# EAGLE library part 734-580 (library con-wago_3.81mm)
Serie 734, Federleiste mit abgewinkelten Einlötstiften / Series 734, Female connector with angled solder pins Polzahl / Pole No.: 20 Bemessungsspannung / Rated Voltage: 160 V Nennstrom / Nominal Current: 10 A Lötstiftlänge: / Solder Pin Length: 3.8 mm Farbe / Color: orange / orange Stand: 01.01.2012. Die jeweils aktuellen Daten zu diesem Artikel finden Sie in unserem Produktkatalog, den Sie unter www.wago.com einsehen können. As of: 01/01/2012. Please find the newest data for this article in our product catalogue, which can be viewed under www.wago.com.
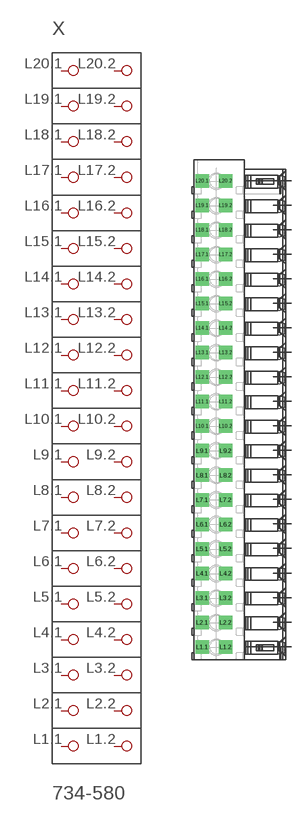
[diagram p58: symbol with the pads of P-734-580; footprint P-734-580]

Designator prefix X

## 734-580  [P-734-580]
L1.1  P1.1
L1.2  P1.2
L2.1  P2.1
L2.2  P2.2
L3.1  P3.1
L3.2  P3.2
L4.1  P4.1
L4.2  P4.2
L5.1  P5.1
L5.2  P5.2
L6.1  P6.1
L6.2  P6.2
L7.1  P7.1
L7.2  P7.2
L8.1  P8.1
L8.2  P8.2
L9.1  P9.1
L9.2  P9.2
L10.1  P10.1
L10.2  P10.2
L11.1  P11.1
L11.2  P11.2
L12.1  P12.1
L12.2  P12.2
L13.1  P13.1
L13.2  P13.2
L14.1  P14.1
L14.2  P14.2
L15.1  P15.1
L15.2  P15.2
L16.1  P16.1
L16.2  P16.2
L17.1  P17.1
L17.2  P17.2
L18.1  P18.1
L18.2  P18.2
L19.1  P19.1
L19.2  P19.2
L20.1  P20.1
L20.2  P20.2

## Footprint P-734-580 (pad centres in mm)
drill 1.4 square: L1.1 -6.127,-36.803; L1.2 -2.477,-36.803; L2.1 -6.127,-32.993; L2.2 -2.477,-32.993; L3.1 -6.127,-29.183; L3.2 -2.477,-29.183; L4.1 -6.127,-25.373; L4.2 -2.477,-25.373; L5.1 -6.127,-21.563; L5.2 -2.477,-21.563; L6.1 -6.127,-17.753; L6.2 -2.477,-17.753; L7.1 -6.127,-13.943; L7.2 -2.477,-13.943; L8.1 -6.127,-10.133; L8.2 -2.477,-10.133; L9.1 -6.127,-6.323; L9.2 -2.477,-6.323; L10.1 -6.127,-2.513; L10.2 -2.477,-2.513; L11.1 -6.127,1.297; L11.2 -2.477,1.297; L12.1 -6.127,5.107; L12.2 -2.477,5.107; L13.1 -6.127,8.917; L13.2 -2.477,8.917; L14.1 -6.127,12.727; L14.2 -2.477,12.727; L15.1 -6.127,16.537; L15.2 -2.477,16.537; L16.1 -6.127,20.347; L16.2 -2.477,20.347; L17.1 -6.127,24.157; L17.2 -2.477,24.157; L18.1 -6.127,27.967; L18.2 -2.477,27.967; L19.1 -6.127,31.777; L19.2 -2.477,31.777; L20.1 -6.127,35.587; L20.2 -2.477,35.587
